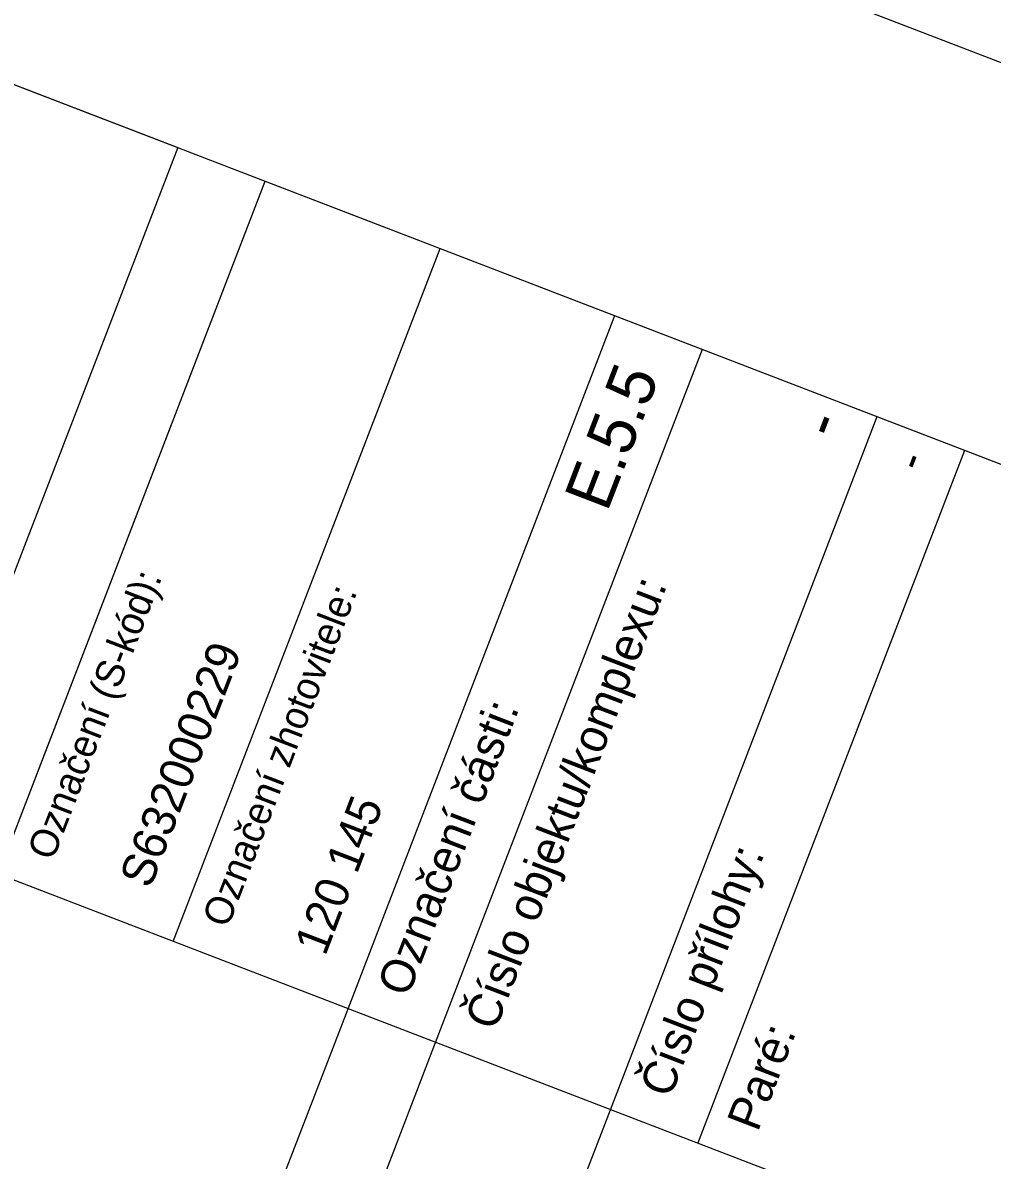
# Model space of a CAD drawing. Extents: x -755344 to -754413, y -1162670 to -1161477.
# Drawn here: x -754523.2 to -754471.5, y -1161726.5 to -1161665.8 of the extents above; entities that cross this region are included whole.
import ezdxf

# ---------------------------------------------------------------- set-up
doc = ezdxf.new("R2010")
doc.units = 0
for name, color, linetype in [('Formát', 7, 'Continuous'), ('SO 11-10-01_popisove_pole', 7, 'Continuous'), ('Vrstva 63', 7, 'Continuous')]:
    doc.layers.add(name, color=color, linetype=linetype)

msp = doc.modelspace()

# ---------------------------------------------------------------- linework, layer by layer
at = {"layer": 'Formát'}
msp.add_line((-754412.582, -1161690.386), (-754689.764, -1161583.712), dxfattribs=at)
at = {"layer": 'SO 11-10-01_popisove_pole'}
for p, q in [((-754515.201, -1161714.808), (-754500.96, -1161677.803)), ((-754505.869, -1161718.399), (-754491.628, -1161681.395)), ((-754501.202, -1161720.195), (-754486.961, -1161683.191)), ((-754491.87, -1161723.787), (-754477.629, -1161686.783)), ((-754487.203, -1161725.583), (-754472.962, -1161688.578)), ((-754552.687, -1161840.051), (-754505.869, -1161718.399)), ((-754548.02, -1161841.847), (-754501.202, -1161720.195)), ((-754538.688, -1161845.439), (-754491.87, -1161723.787))]:
    msp.add_line(p, q, dxfattribs=at)
for points in [[(-754739.341, -1161768.217), (-754678.282, -1161609.561), (-754435.631, -1161702.945), (-754496.69, -1161861.602)], [(-754622.682, -1161813.113), (-754561.623, -1161654.457), (-754514.959, -1161672.416), (-754576.019, -1161831.072)], [(-754571.357, -1161832.88), (-754510.298, -1161674.224), (-754444.969, -1161699.366), (-754506.028, -1161858.022)], [(-754444.964, -1161699.354), (-754459.205, -1161736.358), (-754524.534, -1161711.216), (-754510.293, -1161674.212)]]:
    msp.add_lwpolyline(points, close=True, dxfattribs=at)

# ---------------------------------------------------------------- texts
for s, height, p in [('-', 2.5, (-754479.762, -1161688.086)), ('-', 1.8, (-754475.232, -1161689.804)), ('Označení (S-kód):', 1.5, (-754521.621, -1161710.542)), ('Označení zhotovitele:', 1.5, (-754512.289, -1161714.134)), ('Číslo objektu/komplexu:', 1.8, (-754498.009, -1161719.629)), ('S632000229', 1.8, (-754516.423, -1161712.037)), ('Označení části:', 1.8, (-754502.676, -1161717.833)), ('120 145', 1.8, (-754507.091, -1161715.628)), ('Číslo přílohy:', 1.8, (-754488.677, -1161723.221)), ('Paré:', 1.8, (-754484.01, -1161725.017))]:
    msp.add_text(s, height=height, rotation=68.95068, dxfattribs=at).set_placement(p)
at = {"layer": 'Vrstva 63'}
msp.add_text('E.5.5', height=2.5, rotation=68.95068, dxfattribs=at).set_placement((-754492.044, -1161691.932))

doc.saveas('drawing.dxf')
